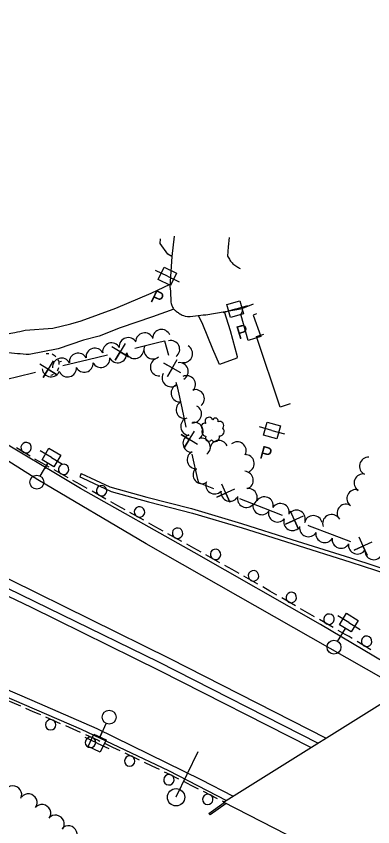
# Model space of a CAD drawing. Extents: x 1746010 to 1754829, y 655801 to 663091.
# Drawn here: x 1746707.7 to 1746912.4, y 662573.6 to 663039.5 of the extents above; entities that cross this region are included whole.
import ezdxf

# ---------------------------------------------------------------- set-up
doc = ezdxf.new("R2010")
doc.units = 0
for name, color, linetype in [('SURVEY - AERIAL SURVEY - Photo Control - Points - Elevations', 7, 'Continuous'), ('SURVEY - AERIAL SURVEY - Photo Control - Points - Locators', 7, 'Continuous'), ('SURVEY - AERIAL SURVEY - Photo Control - Points - Numbers', 7, 'Continuous'), ('SURVEY - AERIAL SURVEY - Photo Control with Text', 7, 'Continuous'), ('SURVEY - CENTERLINE - Existing Roads - Development', 7, 'Continuous'), ('SURVEY - CENTERLINE - Existing Roads Curve Text', 7, 'Continuous'), ('SURVEY - CENTERLINE - Existing Roads Text', 7, 'Continuous')]:
    doc.layers.add(name, color=color, linetype=linetype)

msp = doc.modelspace()

# ---------------------------------------------------------------- linework, layer by layer
at = {"layer": 'SURVEY - AERIAL SURVEY - Photo Control - Points - Elevations'}
for points in [[(1746744.93, 662776.7), (1746744.29, 662774.8), (1746745.52, 662774.11), (1746762.2, 662766.38), (1746783.58, 662760.35), (1746808.97, 662753.87), (1746837.35, 662745.46), (1746866, 662736.39), (1746899.88, 662725.68), (1746928.17, 662716.49), (1746954.76, 662708.38), (1746970.07, 662703.04), (1746980.98, 662697.89), (1746981.99, 662699.95)], [(1746744.93, 662776.7), (1746761.48, 662769), (1746782.76, 662763), (1746808.29, 662756.48), (1746837.05, 662747.95), (1746865.88, 662738.83), (1746899.67, 662728.15), (1746928.08, 662718.92), (1746954.69, 662710.81), (1746970.51, 662705.31), (1746981.99, 662699.95)], [(1746939.36, 662658.3), (1747047.15, 662601.95), (1746935.67, 662531.86), (1746826.79, 662587.8)], [(1746826.79, 662587.8), (1746939.36, 662658.3)]]:
    msp.add_lwpolyline(points, dxfattribs=at)
at = {"layer": 'SURVEY - AERIAL SURVEY - Photo Control - Points - Locators'}
for points in [[(1746929.72, 662652.27), (1746782.27, 662736.35), (1746720.09, 662772.98), (1746670.97, 662804.05), (1746617.8, 662840.77), (1746552.2, 662890.2), (1746497.41, 662932.37), (1746440.73, 662977), (1746415.88, 662996.18), (1746394.18, 663011.61), (1746373.15, 663024.15), (1746347.07, 663039.52)], [(1746937.59, 662657.19), (1746882.34, 662689.89), (1746809.95, 662731.33), (1746744.62, 662768.02), (1746691.33, 662799.82), (1746632.43, 662839.04), (1746574.22, 662880.88), (1746520.31, 662922.22), (1746450.33, 662976.48), (1746412.31, 663005.46)], [(1746201.3, 662955.1), (1746220.85, 662945.8), (1746338.42, 662890.3), (1746446.16, 662838.82), (1746559.49, 662784.93), (1746704.47, 662715.53), (1746795.84, 662670.36), (1746885.61, 662624.64)], [(1746797.09, 662901.5), (1746794.8, 662902.68), (1746790.38, 662908.82), (1746790.5, 662911.54)], [(1746798.36, 662913.07), (1746797.09, 662901.5)], [(1746829.97, 662912.32), (1746829.39, 662906.94), (1746829.08, 662901.57)], [(1746114.66, 662904.92), (1746157.57, 662891.75), (1746193.26, 662877.89), (1746233.13, 662861.28), (1746267.38, 662846.61), (1746300.5, 662831.74), (1746339.16, 662814.51), (1746387.47, 662792.97), (1746429.89, 662773.86), (1746496.22, 662744.14), (1746559.32, 662715.65), (1746615.12, 662691.07), (1746673.07, 662665.19), (1746716.67, 662646.39), (1746754.01, 662630.08), (1746813.77, 662600.8), (1746832.3, 662591.25)], [(1746797.09, 662901.5), (1746795.93, 662884.08)], [(1746108.05, 662901.09), (1746144.78, 662887.93), (1746203.39, 662866.44), (1746249, 662847.4), (1746288.84, 662830.57), (1746354.56, 662801.49), (1746392.63, 662786.06), (1746451.14, 662759.5), (1746507.4, 662733.21), (1746570.91, 662704.8), (1746623.79, 662682.03), (1746692.22, 662652.56), (1746744.98, 662629.82), (1746795.1, 662605.98), (1746828.33, 662588.76)], [(1746712.8, 662859.01), (1746728.76, 662860.2), (1746739.03, 662862.79), (1746744.89, 662864.48), (1746764.85, 662871.76), (1746785.14, 662880.24), (1746796.03, 662885.6)], [(1746843.65, 662874.03), (1746837.53, 662871.5)], [(1746798.11, 662871.18), (1746785.85, 662866.75), (1746767.35, 662860.33), (1746755.36, 662855.6), (1746746.34, 662853.26), (1746731.72, 662848.42), (1746715.1, 662845.01)], [(1746827.03, 662869.72), (1746830.45, 662858.91), (1746834.53, 662844.03), (1746834.43, 662843), (1746824.33, 662839.34), (1746820.59, 662848.23), (1746814.79, 662862.27), (1746812.4, 662867.47)], [(1746816.58, 662867.95), (1746837.53, 662871.5)], [(1746845.62, 662868.51), (1746843.65, 662867.62), (1746848.08, 662855.38), (1746840.89, 662853.04), (1746836.83, 662867.46)], [(1746876.9, 662619.18), (1746790.19, 662663.27), (1746716.47, 662699.65), (1746642.54, 662734.95), (1746569.48, 662769.79)]]:
    msp.add_lwpolyline(points, dxfattribs=at)
for points in [[(1746829.08, 662901.57), (1746830.42, 662899.24), (1746832.12, 662897.26), (1746834.42, 662895.59), (1746836.36, 662894.42)], [(1746795.93, 662884.08), (1746796.35, 662878.71), (1746796.54, 662875.08), (1746797.18, 662872.77), (1746798.41, 662870.88), (1746799.75, 662869.83), (1746801.59, 662868.55), (1746804.6, 662867.19), (1746810.62, 662867.27), (1746816.58, 662867.95)], [(1746715.1, 662845.01), (1746701.61, 662846.11), (1746691.58, 662847.62), (1746684.66, 662850.09), (1746677.97, 662853.92), (1746670.95, 662858.73), (1746663.89, 662863.71), (1746658.44, 662867.47), (1746654.11, 662869.01), (1746650.06, 662870.33), (1746645.98, 662872.7), (1746641.38, 662875.9)], [(1746836.83, 662867.46), (1746836.9, 662868.47), (1746837.64, 662869.95), (1746837.53, 662871.5)], [(1746695.29, 662858.09), (1746696.69, 662858), (1746702.46, 662857.17), (1746706.89, 662857.75), (1746712.8, 662859.01)]]:
    msp.add_spline(points, degree=3, dxfattribs=at)
at = {"layer": 'SURVEY - AERIAL SURVEY - Photo Control - Points - Numbers'}
for points in [[(1746195.86, 662951.95), (1746218.27, 662941.19), (1746316.65, 662894.45), (1746389.22, 662860.05), (1746454.4, 662828.81), (1746528.45, 662793.92), (1746610.6, 662754.65), (1746671.13, 662726.1), (1746733.75, 662695.7), (1746789.4, 662668.49), (1746880.97, 662621.73)], [(1746715.74, 662786.68), (1746707.89, 662791.48)], [(1746722.52, 662782.63), (1746720.39, 662783.83), (1746718.47, 662785.01)], [(1746726.62, 662780.33), (1746722.52, 662782.63)], [(1746737.43, 662774.25), (1746729.41, 662778.76)], [(1746744.32, 662770.38), (1746740.22, 662772.69)], [(1746748.42, 662768.08), (1746744.32, 662770.38)], [(1746759.23, 662762.01), (1746751.21, 662766.51)], [(1746766.11, 662758.14), (1746762.02, 662760.44)], [(1746770.21, 662755.83), (1746766.11, 662758.14)], [(1746781.03, 662749.78), (1746773, 662754.27)], [(1746787.93, 662745.93), (1746783.83, 662748.22)], [(1746792.03, 662743.64), (1746787.93, 662745.93)], [(1746802.86, 662737.59), (1746794.83, 662742.08)], [(1746809.76, 662733.74), (1746805.65, 662736.03)], [(1746813.86, 662731.45), (1746809.76, 662733.74)], [(1746824.68, 662725.4), (1746816.65, 662729.89)], [(1746831.58, 662721.55), (1746827.48, 662723.84)], [(1746835.67, 662719.24), (1746834.32, 662720.01), (1746831.58, 662721.55)], [(1746846.42, 662713.06), (1746838.45, 662717.64)], [(1746853.27, 662709.12), (1746849.19, 662711.46)], [(1746857.34, 662706.78), (1746853.27, 662709.12)], [(1746868.09, 662700.59), (1746860.11, 662705.18)], [(1746874.93, 662696.66), (1746870.86, 662699)], [(1746879.01, 662694.31), (1746874.93, 662696.66)], [(1746889.75, 662688.13), (1746881.78, 662692.72)], [(1746896.6, 662684.19), (1746892.53, 662686.54)], [(1746900.65, 662681.81), (1746898.79, 662682.93), (1746896.6, 662684.19)], [(1746911.24, 662675.37), (1746903.38, 662680.14)], [(1746701.61, 662646.72), (1746710.06, 662643.09)], [(1746713, 662641.83), (1746717.32, 662639.98)], [(1746717.32, 662639.98), (1746720.65, 662638.55), (1746721.63, 662638.11)], [(1746724.56, 662636.81), (1746732.96, 662633.08)], [(1746735.89, 662631.78), (1746740.18, 662629.87)], [(1746740.18, 662629.87), (1746744.47, 662627.96)], [(1746747.4, 662626.66), (1746754.71, 662623.41), (1746755.79, 662622.9)], [(1746758.67, 662621.52), (1746762.91, 662619.49)], [(1746762.91, 662619.49), (1746767.15, 662617.46)], [(1746770.04, 662616.08), (1746778.33, 662612.11)], [(1746781.22, 662610.73), (1746785.46, 662608.71)], [(1746785.46, 662608.71), (1746789.7, 662606.68)], [(1746792.59, 662605.3), (1746795.7, 662603.81), (1746800.83, 662601.22)], [(1746803.69, 662599.77), (1746807.88, 662597.65)], [(1746807.88, 662597.65), (1746812.07, 662595.53)], [(1746814.93, 662594.09), (1746823.14, 662589.94)], [(1746828.23, 662587.06), (1746818.95, 662580.6), (1746818.23, 662581.32), (1746827.09, 662587.64)], [(1746826, 662588.49), (1746827.05, 662587.96)]]:
    msp.add_lwpolyline(points, dxfattribs=at)
for centre, start, end in [((1746713.38, 662791.56), 351.3943, 351.3803), ((1746734.89, 662779.05), 353.5271, 353.5131), ((1746756.69, 662766.8), 353.5271, 353.5131), ((1746778.48, 662754.57), 353.6833, 353.6693), ((1746800.31, 662742.38), 353.6833, 353.6693), ((1746822.13, 662730.19), 353.6833, 353.6693), ((1746843.93, 662717.88), 352.9809, 352.9669), ((1746865.59, 662705.42), 352.9809, 352.9669), ((1746887.26, 662692.96), 352.9809, 352.9669), ((1746908.86, 662680.25), 351.6335, 351.6195), ((1746727.51, 662632.27), 178.9449, 178.9309), ((1746750.34, 662622.12), 178.9449, 178.9309), ((1746772.86, 662611.46), 177.3492, 177.3352), ((1746795.35, 662600.68), 176.1079, 176.0939), ((1746817.66, 662589.4), 176.1079, 176.0939)]:
    msp.add_arc(centre, 3, start, end, dxfattribs=at)
at = {"layer": 'SURVEY - AERIAL SURVEY - Photo Control with Text'}
for p, q in [((1746799.45, 662590.82), (1746812.2, 662616.84)), ((1746799.44, 662590.61), (1746799.44, 662590.61))]:
    msp.add_line(p, q, dxfattribs=at)
msp.add_circle((1746799.47, 662590.62), 5, dxfattribs=at)
at = {"layer": 'SURVEY - CENTERLINE - Existing Roads - Development'}
for points in [[(1746864.9, 662816.71), (1746859.17, 662814.8), (1746845.68, 662855.4), (1746849.82, 662856.77)], [(1746770.23, 662851.42), (1746764.45, 662841.79), (1746767.29, 662846.59), (1746772.12, 662843.65), (1746762.55, 662849.56)], [(1746790.33, 662852.08), (1746775.76, 662848.55)], [(1746795.31, 662844.44), (1746793.05, 662852.73), (1746790.33, 662852.08)], [(1746728.95, 662841.42), (1746723.16, 662831.79), (1746726.01, 662836.6), (1746730.84, 662833.65), (1746721.27, 662839.56)], [(1746749.05, 662842.08), (1746734.48, 662838.55)], [(1746760.12, 662844.76), (1746749.05, 662842.08)], [(1746802.22, 662834.56), (1746792.5, 662840.03), (1746797.35, 662837.34), (1746794.58, 662832.42), (1746800.15, 662842.17)], [(1746707.77, 662832.08), (1746698.03, 662829.72), (1746693.99, 662832.62)], [(1746718.84, 662834.76), (1746707.77, 662832.08)], [(1746802.91, 662814.43), (1746800.43, 662825.66), (1746799.54, 662828.93)], [(1746805.35, 662803.4), (1746802.91, 662814.43)], [(1746811.75, 662793.31), (1746802.34, 662799.11), (1746807.03, 662796.26), (1746804.03, 662791.47), (1746810.06, 662800.96)], [(1746812.01, 662773.3), (1746808.8, 662787.82)], [(1746821.09, 662767.92), (1746812.45, 662771.29), (1746812.01, 662773.3)], [(1746833.1, 662767.61), (1746822.96, 662763.02), (1746827.98, 662765.33), (1746830.28, 662760.17), (1746825.78, 662770.47)], [(1746849.91, 662756.67), (1746836.01, 662762.09)], [(1746860.48, 662752.54), (1746849.91, 662756.67)], [(1746872.49, 662752.24), (1746862.35, 662747.65), (1746867.37, 662749.96), (1746869.67, 662744.79), (1746865.17, 662755.09)], [(1746889.32, 662741.43), (1746876.08, 662746.45), (1746875.4, 662746.72)], [(1746899.89, 662737.41), (1746889.32, 662741.43)], [(1746911.87, 662737.22), (1746901.81, 662732.53), (1746906.79, 662734.9), (1746909.14, 662729.75), (1746904.54, 662740.01)]]:
    msp.add_lwpolyline(points, dxfattribs=at)
at = {"layer": 'SURVEY - CENTERLINE - Existing Roads Curve Text'}
for p, q in [((1746794.49, 662890.03), (1746787.74, 662893.3)), ((1746794.49, 662890.03), (1746801.24, 662886.76)), ((1746833.42, 662871.17), (1746840.6, 662873.33)), ((1746833.42, 662871.17), (1746826.23, 662869.01)), ((1746733.6, 662840.97), (1746732.24, 662840.67)), ((1746854.53, 662801.45), (1746847.3, 662803.46)), ((1746854.53, 662801.45), (1746861.75, 662799.45)), ((1746727.88, 662785.92), (1746721.42, 662789.74)), ((1746727.88, 662785.92), (1746734.33, 662782.11)), ((1746721.47, 662775.07), (1746725.89, 662782.57)), ((1746725.69, 662782.22), (1746724.06, 662779.46)), ((1746898.67, 662690.97), (1746892.25, 662694.86)), ((1746892.15, 662680.19), (1746896.65, 662687.64)), ((1746896.44, 662687.3), (1746894.79, 662684.56)), ((1746898.67, 662690.97), (1746905.09, 662687.09)), ((1746759.42, 662633.13), (1746755.75, 662625.24)), ((1746755.92, 662625.61), (1746757.27, 662628.51)), ((1746754.1, 662621.71), (1746747.3, 662624.88)), ((1746754.1, 662621.71), (1746760.89, 662618.54))]:
    msp.add_line(p, q, dxfattribs=at)
for points in [[(1746792.68, 662895.24), (1746799.7, 662891.84), (1746796.3, 662884.82), (1746789.28, 662888.22)], [(1746828.56, 662873.78), (1746836.03, 662876.02), (1746838.27, 662868.55), (1746830.8, 662866.31)], [(1746851.81, 662806.26), (1746859.33, 662804.17), (1746857.24, 662796.65), (1746849.73, 662798.74)], [(1746733.22, 662787.3), (1746729.25, 662780.58), (1746722.54, 662784.55), (1746726.5, 662791.27)], [(1746904.03, 662692.29), (1746899.99, 662685.62), (1746893.31, 662689.66), (1746897.35, 662696.33)], [(1746748.91, 662619.83), (1746752.21, 662626.89), (1746759.28, 662623.6), (1746755.98, 662616.53)]]:
    msp.add_lwpolyline(points, close=True, dxfattribs=at)
for centre in [(1746719.48, 662771.72), (1746890.13, 662676.86), (1746761.07, 662636.67)]:
    msp.add_circle(centre, 4, dxfattribs=at)
for start, end in [(87.6602, 101.5496), (46.0364, 70.8064), (359.9946, 26.5099), (324.3515, 344.694), (282.4736, 297.0945)]:
    msp.add_arc((1746726.19, 662839.28), 6.25, start, end, dxfattribs=at)
at = {"layer": 'SURVEY - CENTERLINE - Existing Roads Text'}
msp.add_circle((1746820.59, 662801.98), 0.0807, dxfattribs=at)
for centre, radius, start, end in [((1746791.11, 662854.33), 5.13, 22.7288, 179.5223), ((1746771.95, 662849.67), 5.13, 29.0683, 185.8618), ((1746781.39, 662852.4), 5.13, 22.7288, 179.5223), ((1746762.43, 662846.64), 5.13, 29.0683, 185.8618), ((1746786.11, 662847.68), 5.13, 152.7304, 309.5239), ((1746796.42, 662848), 5.13, 306.8819, 103.6754), ((1746743.31, 662840.75), 5.13, 28.0114, 184.8048), ((1746752.89, 662843.61), 5.13, 28.0114, 184.8048), ((1746765.96, 662845.46), 5.13, 207.2436, 4.037), ((1746775.77, 662847.83), 5.13, 199.2217, 356.0151), ((1746803.82, 662845.56), 5.13, 263.3061, 60.0996), ((1746733.72, 662837.9), 5.13, 28.0114, 184.8048), ((1746756.35, 662842.74), 5.13, 207.2436, 4.037), ((1746789.82, 662837.9), 5.13, 116.5886, 273.382), ((1746727.71, 662837.35), 5.13, 184.7034, 341.4968), ((1746737.14, 662837.3), 5.13, 207.2436, 4.037), ((1746746.74, 662840.02), 5.13, 207.2436, 4.037), ((1746801.3, 662835.29), 5.13, 300.8729, 97.6664), ((1746796.58, 662831.65), 5.13, 151.2991, 308.0925), ((1746805.49, 662827.8), 5.13, 318.24, 115.0334), ((1746801.7, 662822.91), 5.13, 118.7042, 275.4977), ((1746810.59, 662819.77), 5.13, 309.3171, 106.1106), ((1746804.63, 662813.39), 5.13, 118.7042, 275.4977), ((1746808.99, 662810.94), 5.13, 265.3398, 62.1333), ((1746807.28, 662803.68), 5.13, 109.2743, 266.0678), ((1746818.41, 662806.7), 2.31, 20.8366, 214.2563), ((1746822.06, 662806.96), 1.59, 340.816, 159.5616), ((1746809.86, 662800.99), 5.13, 303.6361, 100.4295), ((1746815.72, 662803.82), 1.76, 63.4553, 240.7745), ((1746824.55, 662804.35), 2.31, 318.6998, 115.4887), ((1746808.54, 662793.98), 5.13, 109.2743, 266.0678), ((1746816.73, 662800.65), 2.49, 138.7424, 265.588), ((1746824.44, 662800.96), 2.64, 267.7525, 45.2768), ((1746814.02, 662791.91), 5.13, 307.906, 104.6995), ((1746818.2, 662797.17), 1.93, 148.9013, 323.9016), ((1746824.07, 662790.57), 5.13, 24.2807, 181.0741), ((1746821.8, 662797.67), 2.62, 218.6484, 14.4869), ((1746834.62, 662789.76), 5.13, 333.2323, 130.0257), ((1746810.99, 662784.56), 5.13, 117.4242, 274.2177), ((1746839.22, 662782.42), 5.13, 295.0852, 91.8786), ((1746909.88, 662780.89), 5.13, 86.5449, 243.3384), ((1746814.35, 662775.97), 5.13, 141.9042, 298.6977), ((1746838.7, 662772.83), 5.13, 289.5348, 86.3283), ((1746906.83, 662771.31), 5.13, 80.2523, 237.0457), ((1746821.64, 662770.06), 5.13, 158.8708, 315.6643), ((1746830.38, 662765.86), 5.13, 171.5114, 328.3048), ((1746840.89, 662762.97), 5.13, 301.8919, 98.6853), ((1746902.69, 662762.3), 5.13, 76.0147, 232.8081), ((1746839.79, 662762.32), 5.13, 166.508, 323.3015), ((1746850.15, 662758.13), 5.13, 349.1486, 145.942), ((1746848.7, 662758.14), 5.13, 166.508, 323.3015), ((1746859.35, 662754.33), 5.13, 349.1486, 145.942), ((1746897.03, 662753.97), 5.13, 66.4745, 223.2679), ((1746857.65, 662753.92), 5.13, 162.3813, 319.1747), ((1746868.55, 662750.54), 5.13, 349.1486, 145.942), ((1746878.29, 662747.39), 5.13, 12.0739, 168.8674), ((1746888.73, 662747.97), 5.13, 44.007, 200.8005), ((1746866.38, 662749.05), 5.13, 162.3813, 319.1747), ((1746875.46, 662745.45), 5.13, 171.7576, 328.551), ((1746884.79, 662742.1), 5.13, 172.3107, 329.1042), ((1746894.16, 662738.83), 5.13, 172.2735, 329.067), ((1746903.57, 662735.54), 5.13, 172.2735, 329.067), ((1746912.98, 662732.28), 5.13, 172.8269, 329.6203)]:
    msp.add_arc(centre, radius, start, end, dxfattribs=at)
for centre, major_axis in [((1746705.95, 662592.38), (4.47, -2.24)), ((1746714.79, 662587.77), (3.95, -3.07)), ((1746722.66, 662581.64), (3.95, -3.07)), ((1746730.43, 662575.51), (3.86, -3.18)), ((1746737.87, 662569.4), (3.86, -3.18))]:
    msp.add_ellipse(centre, major_axis=major_axis, ratio=0.940188, start_param=0, end_param=3.141593, dxfattribs=at)

# ---------------------------------------------------------------- texts
at = {"layer": 'SURVEY - CENTERLINE - Existing Roads Curve Text'}
for rotation, p in [(334.1476, (1746784.16, 662875.81)), (16.7195, (1746835.43, 662853.71)), (344.4784, (1746846.91, 662785.61))]:
    msp.add_text('P', height=7.48, rotation=rotation, dxfattribs=at).set_placement(p)

doc.saveas('drawing.dxf')
